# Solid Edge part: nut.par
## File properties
Author: Sarvanan
Template: sync ansi part.par
Last saved by: CADCIM
Revision: 18
Application: Solid Edge
Accuracy: 0.990
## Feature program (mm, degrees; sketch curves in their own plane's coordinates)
sketch for "Hole_1" plane through (27.3343, 36.5222, 2.54) normal (0, 0, 1) x-axis (1, 0, 0)
  hole centre (-0.0483, 0.0372) bore radius 3.302
hole "Hole_1" diameter 6.604 through
pattern "unnamed Pattern 1" of "Hole_1"
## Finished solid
Body 1: solid body, 11 faces, 22 edges, 12 vertices.
  Faces by surface: plane 8, cone 2, cylinder 1
  Edges by curve: intersection 12, line 6, circle 4
Bounding box of the edges (mm): 10.265 x 8.890 x 5.080, from (22.2017, 32.1144, -2.54) to (32.467, 41.0044, 2.54).
Cylindrical faces by radius (mm): R3.302 x1
Conical faces (half-angle, radius in mm at the cone's reference point): 45 deg R5.1326 x2
Planar faces by outward normal: +y 1, +z 1, -y 1, -z 1, oblique 4
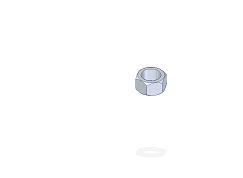
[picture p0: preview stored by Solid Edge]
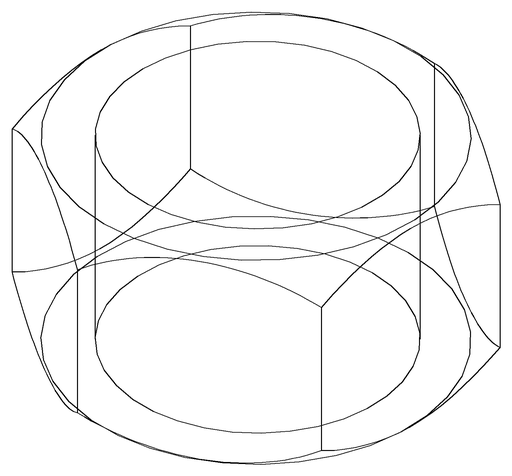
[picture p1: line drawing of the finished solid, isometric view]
